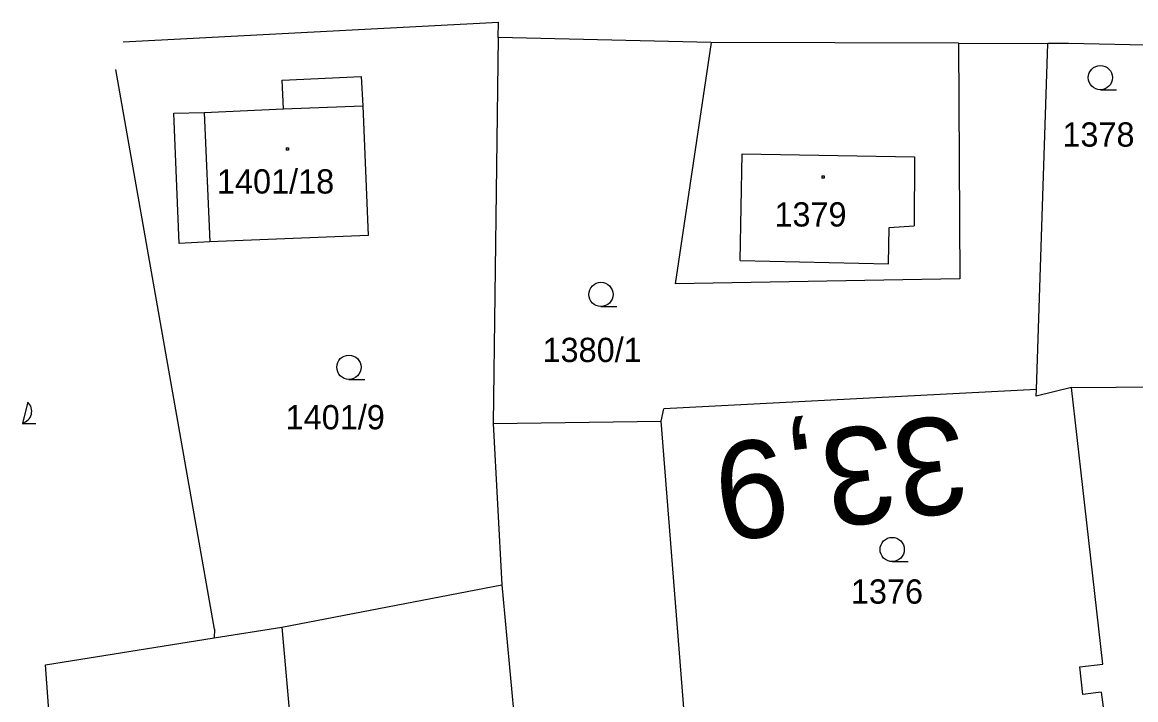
# Model space of a CAD drawing. Extents: x -805011 to -803920, y -1150790 to -1150234.
# Drawn here: x -804775.7 to -804706.8, y -1150469 to -1150427.1 of the extents above; entities that cross this region are included whole.
import ezdxf

# ---------------------------------------------------------------- set-up
doc = ezdxf.new("R2010")
doc.units = 0
for name, color, linetype in [('Default', 7, 'Continuous'), ('kilometráž - vrstava 7', 7, 'Continuous'), ('kn_celek - Cisla pozemkovych parcel', 7, 'Continuous'), ('kn_celek - Cisla stavebnich parcel', 7, 'Continuous'), ('kn_celek - Hranice parcel', 7, 'Continuous'), ('kn_celek - Vnitrni kresby', 7, 'Continuous'), ('kn_celek - Znacky budov', 7, 'Continuous'), ('kn_celek - Znacky kultur', 7, 'Continuous')]:
    doc.layers.add(name, color=color, linetype=linetype)

# ---------------------------------------------------------------- blocks, each defined once
blk = doc.blocks.new('304')
at = {"layer": 'Default'}
blk.add_line((-0.07, 0), (9.85, 0), dxfattribs=at)
blk.add_circle((-0.08, 7.5), 7.5, dxfattribs=at)
blk = doc.blocks.new('402')
at = {"layer": 'Default'}
for p, q in [((-0.77, 0.75), (0.73, 0.75)), ((-0.77, 0.75), (-0.77, -0.75)), ((0.73, 0.75), (0.73, -0.75)), ((0.73, -0.75), (-0.77, -0.75))]:
    blk.add_line(p, q, dxfattribs=at)

msp = doc.modelspace()

# ---------------------------------------------------------------- linework, layer by layer
at = {"layer": 'Default'}
for p, q in [((-804775.32, -1150450.608), (-804775.659, -1150451.891)), ((-804775.664, -1150451.91), (-804774.835, -1150451.91))]:
    msp.add_line(p, q, dxfattribs=at)
msp.add_arc((-804775.828, -1150451.16), 0.75, 282.99534, 47.36135, dxfattribs=at)
at = {"layer": 'kn_celek - Hranice parcel'}
for p, q in [((-804769.422, -1150428.321), (-804746.2, -1150427.11)), ((-804746.23, -1150428.06), (-804746.2, -1150427.11)), ((-804746.23, -1150428.06), (-804746.54, -1150451.93)), ((-804733.05, -1150428.36), (-804746.23, -1150428.06)), ((-804733.05, -1150428.36), (-804735.28, -1150443.28)), ((-804717.75, -1150428.4), (-804733.05, -1150428.36)), ((-804717.75, -1150428.4), (-804712.23, -1150428.42)), ((-804717.75, -1150428.4), (-804717.67, -1150442.98)), ((-804712.93, -1150449.81), (-804712.23, -1150428.42)), ((-804710.95, -1150428.42), (-804712.23, -1150428.42)), ((-804688.79, -1150428.9), (-804710.95, -1150428.42)), ((-804763.78, -1150464.64), (-804769.875, -1150430.034)), ((-804759.58, -1150430.69), (-804754.7, -1150430.47)), ((-804759.5, -1150432.47), (-804759.58, -1150430.69)), ((-804754.7, -1150430.47), (-804754.6, -1150432.27)), ((-804754.6, -1150432.27), (-804754.27, -1150440.29)), ((-804766.29, -1150432.74), (-804764.41, -1150432.68)), ((-804765.96, -1150440.79), (-804766.29, -1150432.74)), ((-804764.41, -1150432.68), (-804759.5, -1150432.47)), ((-804764.06, -1150440.69), (-804765.96, -1150440.79)), ((-804754.27, -1150440.29), (-804764.06, -1150440.69)), ((-804717.67, -1150442.98), (-804735.28, -1150443.28)), ((-804710.75, -1150449.7), (-804684.79, -1150449.44)), ((-804712.93, -1150449.81), (-804735.98, -1150451.02)), ((-804710.75, -1150449.7), (-804712.95, -1150450.24)), ((-804712.95, -1150450.24), (-804712.93, -1150449.81)), ((-804710.06, -1150455.87), (-804710.75, -1150449.7)), ((-804736.15, -1150451.78), (-804735.98, -1150451.02)), ((-804746.54, -1150451.93), (-804736.15, -1150451.78)), ((-804746.54, -1150451.93), (-804746, -1150461.9)), ((-804734.44, -1150473.15), (-804736.15, -1150451.78)), ((-804708.82, -1150466.81), (-804710.06, -1150455.87)), ((-804759.6, -1150464.51), (-804746, -1150461.9)), ((-804746, -1150461.9), (-804743.58, -1150488.04)), ((-804763.8, -1150465.18), (-804759.6, -1150464.51)), ((-804763.78, -1150464.64), (-804763.8, -1150465.18)), ((-804759.6, -1150464.51), (-804757.39, -1150489.7)), ((-804774.23, -1150466.84), (-804763.8, -1150465.18)), ((-804774.01, -1150469.95), (-804774.23, -1150466.84)), ((-804710.25, -1150466.97), (-804708.82, -1150466.81)), ((-804710.06, -1150468.67), (-804710.25, -1150466.97)), ((-804708.92, -1150468.54), (-804710.06, -1150468.67)), ((-804708.92, -1150468.54), (-804708.56, -1150471.29))]:
    msp.add_line(p, q, dxfattribs=at)
at = {"layer": 'kn_celek - Vnitrni kresby'}
for p, q in [((-804759.5, -1150432.47), (-804754.6, -1150432.27)), ((-804764.41, -1150432.68), (-804764.06, -1150440.69)), ((-804731.26, -1150441.85), (-804731.12, -1150435.25)), ((-804731.12, -1150435.25), (-804720.47, -1150435.44)), ((-804720.47, -1150435.44), (-804720.48, -1150439.69)), ((-804722.07, -1150442.04), (-804722.03, -1150439.8)), ((-804722.03, -1150439.8), (-804720.48, -1150439.69)), ((-804731.26, -1150441.85), (-804722.07, -1150442.04))]:
    msp.add_line(p, q, dxfattribs=at)

# ---------------------------------------------------------------- block references
at = {"layer": 'kn_celek - Znacky budov', "xscale": 0.1, "yscale": 0.10000000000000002}
for p in [(-804759.27, -1150434.94), (-804726.13, -1150436.68)]:
    msp.add_blockref('402', p, dxfattribs=at)
at = {"layer": 'kn_celek - Znacky kultur', "xscale": 0.1, "yscale": 0.10000000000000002}
for p in [(-804708.96, -1150431.28), (-804739.86, -1150444.69), (-804755.45, -1150449.19), (-804721.84, -1150460.46)]:
    msp.add_blockref('304', p, dxfattribs=at)

# ---------------------------------------------------------------- texts
at = {"layer": 'kilometráž - vrstava 7'}
msp.add_text('33,9', height=6, rotation=187.25424, dxfattribs=at).set_placement((-804717.65, -1150451.318))
at = {"layer": 'kn_celek - Cisla pozemkovych parcel'}
for s, p in [('1378', (-804711.32, -1150434.8)), ('1380/1', (-804743.479, -1150448.12)), ('1401/9', (-804759.371, -1150452.28)), ('1376', (-804724.404, -1150463.06))]:
    msp.add_text(s, height=1.5, dxfattribs=at).set_placement(p)
at = {"layer": 'kn_celek - Cisla stavebnich parcel'}
for s, p in [('1401/18', (-804763.619, -1150437.7)), ('1379', (-804729.134, -1150439.74))]:
    msp.add_text(s, height=1.5, dxfattribs=at).set_placement(p)

doc.saveas('drawing.dxf')
